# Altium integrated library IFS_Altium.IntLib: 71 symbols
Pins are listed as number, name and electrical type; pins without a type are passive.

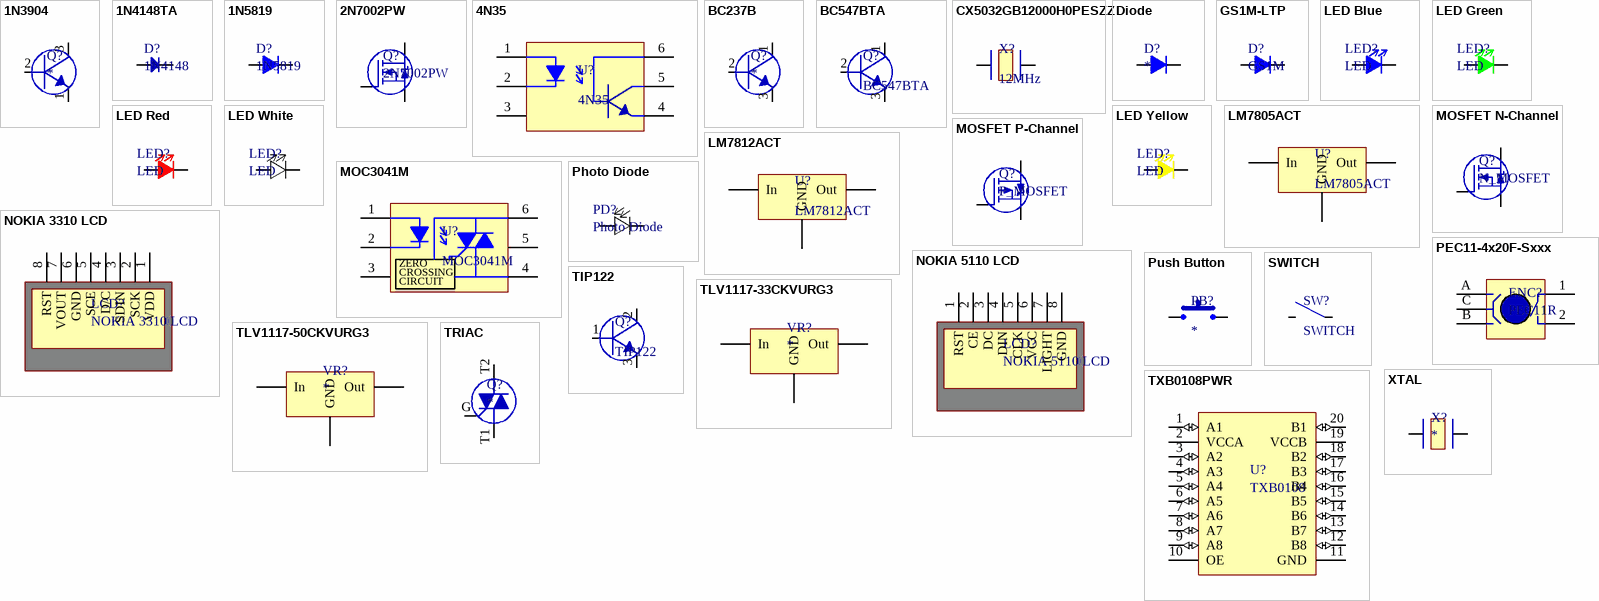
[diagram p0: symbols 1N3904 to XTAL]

## 1N3904
designator Q?
1N3904 NPN Transistor
footprint TO92-2.54 (TO92, 2.54 pitch)
pins: 1, 2, 3

## 1N4148TA
designator D?, comment 1N4148
Diodes - General Purpose, Power, Switching Hi Conductance Fast; Manufacturer: Fairchild Semiconductor; Manufacturer Part Number: 1N4148TA; Configuration: Single; Forward Continuous Current: 0.2 A; Max Surge Current: 4 A; Recovery Time: 4 ns; Forward Voltage Drop: 1 V; Maximum Power Dissipation: 0.5 W; Peak Reverse Voltage: 100 V
footprint DO-35 Glass (DO-35 Glass 4mils)
pins: 1, 2

## 1N5819
designator D?
Schottky diode
footprint DO-214AC (DO-214AC, SMA)
pins: 1, 2

## 2N7002PW
designator Q?
MOSFET 60V 0.3A N-CHANNEL TRENCH MOSFET; Manufacturer: NXP Semiconductors; Manufacturer Part Number: 2N7002PW,115; Configuration: Single; Continuous Drain Current: 310 mA; Rds On: 1 Ohms; Fall Time: 4 ns; Pd - Power Dissipation: 260 mW; Qg - Gate Charge: 0.6 nC; Typical Turn-Off Delay Time: 10 ns; Vgs - Gate-Source Breakdown Voltage: 20 V
footprint SOT323 (SOT323, 3 pins)
pins: 1 G, 2 S, 3 D

## 4N35
designator U?
Transistor Output Optocouplers PTR 100%, 3.5KV; Manufacturer: Lite-On; Input Type: DC; Isolation Voltage: 3550 Vrms; Output Device: NPN Phototransistor; Maximum Collector Current: 100 mA; Maximum Collector Emitter Saturation Voltage: 0.3 V; Maximum Collector Emitter Voltage: 30 V; Maximum Forward Diode Voltage: 1.5 V; Maximum Input Diode Current: 60 mA; Maximum Power Dissipation: 350 mW; Maximum Reverse Diode Voltage: 6 V; Number of Channels per Chip: 1 Channel
footprint PDIP6-300
pins: 1 (power), 2, 3, 4, 5, 6

## BC237B
designator Q?
BC237B NPN Transistor
footprint TO92-2.54 (TO92, 2.54 pitch)
pins: 1, 2, 3

## BC547BTA
designator Q?
TRANS NPN 45V 100MA TO-92; Manufacturer: Fairchild Semiconductor; Vce Saturation (Max) @ Ib, Ic: 600mV @ 5mA, 100mA; DC Current Gain (hFE) (Min) @ Ic, Vce: 200 @ 2mA, 5V; Power - Max: 500mW; Frequency - Transition: 300MHz
footprint TO92-2.54 (TO92, 2.54 pitch)
pins: 1, 2, 3

## CX5032GB12000H0PESZZ
designator X?, comment 12MHz
Crystals 12000kHz 12pF; Manufacturer: AVX; Manufacturer Part Number: CX5032GB12000H0PESZZ; Frequency Stability: 20 PPM
footprint 2-SMD
pins: 1, 2

## Diode
designator D?
Diode, generic
pins: 1, 2

## GS1M-LTP
designator D?, comment GS1M
Rectifiers 1000V,1A; Manufacturer: Micro Commercial Components (MCC); Manufacturer Part Number: GS1M-LTP; Max Surge Current: 30 A; Reverse Current IR: 10 uA
footprint DO-214AC (DO-214AC, SMA)
pins: 1, 2

## LED Blue
designator LED?, comment LED
LED Blue
footprint LED Blue 3mm TH V
pins: 1, 2

## LED Green
designator LED?, comment LED
LED Green
footprint LED Green 3mm TH V
pins: 1, 2

## LED Red
designator LED?, comment LED
LED Red
footprint LED Red 3mm TH V
pins: 1, 2

## LED White
designator LED?, comment LED
LED White
footprint LED White 3mm TH V
pins: 1, 2

## LED Yellow
designator LED?, comment LED
LED Yellow
footprint LED Yellow 3mm TH V
pins: 1, 2

## LM7805ACT
designator U?
IC REG LDO 5V 1A TO220-3; Manufacturer: Fairchild Semiconductor; Regulator Topology: Positive Fixed; Voltage - Dropout (Typical): 2V @ 1A; Number of Regulators: 1; Voltage - Input: Up to 35V
footprint TO220-3 (TO220, 3 Pins)
pins: 1 In (power), 2 GND (power), 3 Out (power)

## LM7812ACT
designator U?
IC REG LDO 12V 1A TO220-3; Manufacturer: Fairchild Semiconductor; Regulator Topology: Positive Fixed; Voltage - Dropout (Typical): 2V @ 1A; Number of Regulators: 1; Voltage - Input: Up to 35V
footprint TO220-3 (TO220, 3 Pins)
pins: 1 In (power), 2 GND (power), 3 Out (power)

## MOC3041M
designator U?
Triac & SCR Output Optocouplers DIP-6 ZERO TRIAC; Manufacturer: Fairchild Semiconductor; Isolation Voltage: 5250 Vrms; Output Device: PhotoTriac; Output Type: AC; Forward Current: 60 mA; Forward Voltage: 1.25 V; Power Dissipation: 250 mW; Maximum Trigger Current: 15 mA; Number of Channels per Chip: 1 Channel; Off-state Output Voltage - VDRM: 400 V; Zero-Crossing Circuit: With Zero-Crossing Circuit; Zero-Crossing Voltage: 20 V
footprint PDIP6-300-W (PDIP6-300 White)
pins: 1 (power), 2, 3, 4, 5, 6

## MOSFET N-Channel
designator Q?, comment N_MOSFET
Generic N-Channel MOSFET
footprint SOT323 (SOT323, 3 pins)
pins: 1 G, 2 S, 3 D

## MOSFET P-Channel
designator Q?, comment P_MOSFET
Generic P-Channel MOSFET
footprint SOT323 (SOT323, 3 pins)
pins: 1 G, 2 S, 3 D

## NOKIA 3310 LCD
designator LCD?
footprint NOKIA 3310 LCD
pins: 1 VDD, 2 SCK, 3 SDIN, 4 D/C, 5 SCE, 6 GND, 7 VOUT, 8 RST

## NOKIA 5110 LCD
designator LCD?
footprint NOKIA 5110 LCD
pins: 1 RST, 2 CE, 3 DC, 4 DIN, 5 CLK, 6 VCC, 7 LIGHT, 8 GND

## PEC11-4x20F-Sxxx
designator ENC?, comment PEC11R
Encoders 20mm SHAFT w/SWITCH; Manufacturer: Bourns; Manufacturer Part Number: PEC11R-4220F-S0024; Number of Detents: 24; Output: Quadrature; Resolution: 24 PPR; With Switch: Switch; Number of Channels: 2 Channel; Shaft Type: Flatted; Product Status: New Product
footprint PEC11-4x20F-Sxxx (Incrmental Encoder with momentary puch switch)
pins: 1, 2, A, B, C, GND (power) hidden to GND

## Photo Diode
designator PD?
footprint LED White 3mm TH V
pins: 1, 2

## Push Button
designator PB?
Push Button
footprint Tack Switch 6x6 1mm TH (Tack Switch 6x6mm, 1mm button height TH)
pins: 1, 2

## SWITCH
designator SW?
Switch, generic
footprint 1x2x5.08 Pin Header TH V
pins: 1, 2

## TIP122
designator Q?
TRANS NPN DARL 100V 5A TO-220; Manufacturer: Fairchild Semiconductor; Transistor Type: NPN - Darlington; Vce Saturation (Max) @ Ib, Ic: 4V @ 20mA, 5A; Current - Collector Cutoff (Max): 500µA; DC Current Gain (hFE) (Min) @ Ic, Vce: 1000 @ 3A, 3V; Power - Max: 2W
footprint TO220-3 (TO220, 3 Pins)
pins: 1, 2, 3

## TLV1117-33CKVURG3
designator VR?
LDO Voltage Regulators Sgl Output LDO 800mA Fixed Int Crnt limit; Manufacturer: Texas Instruments; Input Bias Current - Max: 5 mA; Input Voltage MAX: 15 V; Number of Outputs: 1 Output; Output Voltage: 3.3 V; Dropout Voltage - Max: 1.2 V at 100 mA, 1.25 V at 500 mA, 1.3 V at 800 mA; Input Voltage MIN: + 4.7 V; Line Regulation: 0.2 %; Load Regulation: 0.4 %
footprint TO252-2 (TO252, 2 Pins)
pins: 1 GND, 2 Out, 3 In

## TLV1117-50CKVURG3
designator VR?
LDO Voltage Regulators Sgl Output LDO 800mA Fixed Int Crnt limit; Manufacturer: Texas Instruments; Manufacturer Part Number: TLV1117-50CKVURG3; Input Bias Current - Max: 5 mA; Input Voltage MAX: 15 V; Number of Outputs: 1 Output; Output Voltage: 5 V; Dropout Voltage - Max: 1.2 V at 100 mA, 1.25 V at 500 mA, 1.3 V at 800 mA; Input Voltage MIN: + 6.4 V; Line Regulation: 0.2 %; Load Regulation: 0.4 %
footprint TO252-2 (TO252, 2 Pins)
pins: 1 GND, 2 Out, 3 In

## TRIAC
designator Q?
TRIAC, Generic
pins: G, T1, T2

## TXB0108PWR
designator U?, comment TXB0108
Translation - Voltage Levels 8-Bit Bi-directional; Manufacturer: Texas Instruments; Manufacturer Part Number: TXB0108PWR; Propagation Delay Time: 9.5 ns; Supply Voltage - Max: 3.6 V, 5.5 V; Supply Voltage - Min: 1.2 V, 1.65 V
footprint TSSOP20
pins: 1 A1 (io), 2 VCCA (power), 3 A2 (io), 4 A3 (io), 5 A4 (io), 6 A5 (io), 7 A6 (io), 8 A7 (io), 9 A8 (io), 10 OE, 11 GND (power), 12 B8 (io), 13 B7 (io), 14 B6 (io), 15 B5 (io), 16 B4 (io), 17 B3 (io), 18 B2 (io), 19 VCCB (power), 20 B1 (io)

## XTAL
designator X?
Crystal, Generic
footprint HC-49U (HC-49U XTAL)
footprint HC-49US (HC-49US XTAL)
footprint HC-49US - SMD (HC-49US XTAL)
footprint Cilindrical-H-SMD (Cilindrical canned XTAL, Horizontal, SMD)
footprint 2-SMD
pins: 1, 2


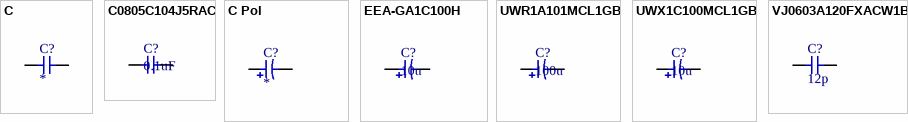
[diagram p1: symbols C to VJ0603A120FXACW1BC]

## C
designator C?
Capacitor, generic
footprint C Disc 5x2.5-2.5
footprint C0603-0.80 (Capacitor Chip 0603 Height 0.80mm)
footprint C0805-0.80 (Capacitor Chip 0805 Height 0.80)
footprint C0805-1.25 (Capacitor Chip 0805 Height 1.25mm)
footprint C1206-0.80 (Capacitor Chip 1206 Height 0.80mm)
footprint C1206-1.00 (Capacitor Chip 1206 Height 1.00mm)
footprint C1206-1.25 (Capacitor Chip 1206 Height 1.25mm)
footprint C1206-1.60 (Capacitor Chip 1206 Height 1.60mm)
footprint C1210-0.80 (Capacitor Chip 1210 Height 0.80mm)
footprint C1210-1.00 (Capacitor Chip 1210 Height 1.00mm)
footprint C1210-1.25 (Capacitor Chip 1210 Height 1.25mm)
footprint C1210-1.60 (Capacitor Chip 1210 Height 1.60mm)
footprint C1210-1.90 (Capacitor Chip 1210 Height 1.90mm)
footprint C1210-2.10 (Capacitor Chip 1210 Height 2.10mm)
footprint C1210-2.50 (Capacitor Chip 1210 Height 2.50mm)
footprint C Disc 8x2.5-5.0 (C Disc 5x2.5-5.0)
pins: 1, 2

## C0805C104J5RAC
designator C?, comment 0.1uF
Multilayer Ceramic Capacitors MLCC - SMD/SMT 50volts 0.1uF 5% X7R; Manufacturer: Kemet; Manufacturer Part Number: C0805C104J5RAC; Type: SMD MLCCs X7R, Commercial; Voltage Rating: 50 V; Case Height: 0.9 mm; Case Length: 2 mm; Case Width: 1.2 mm; Class: 2; Dissipation Factor DF: 2.5
footprint C0805-0.80 (Capacitor Chip 0805 Height 0.80)
pins: 1, 2

## C Pol
designator C?
Capacitor, polarized, generic
footprint C Elec SMD 6.3x5.4 (C Elec SMD 6.3x5.4, Generic Value)
footprint C Elec TH V 4x7-2.5 (C Elec TH 4x7 2.5mm pitch)
footprint C Elec TH V 18x35-7.5 (C Elec TH 18x35 7.5mm pitch)
pins: 1, 2

## EEA-GA1C100H
designator C?, comment 10u
Aluminium Electrolytic Capacitors - Leaded 16volts 10uF 4X7mm L/S=2.5mm Ammo STR; Manufacturer: Panasonic; Manufacturer Part Number: EEA-GA1C100H; Tolerance: 20 %; Voltage Rating DC: 16 V; Leakage Current: 3 uA; Case Diameter: 4 mm; Case Length: 7 mm; Load Life: 1000 h; Ripple Current: 30 mA
footprint C Elec TH V 4x7-2.5 (C Elec TH 4x7 2.5mm pitch)
pins: 1, 2

## UWR1A101MCL1GB
designator C?, comment 100u
Aluminium Electrolytic Capacitors - SMD 100UF    10V; Manufacturer: Nichicon; Manufacturer Part Number: UWR1A101MCL1GB; Tolerance: 20 %; Leakage Current: 75.2 uA; Case Diameter: 5 mm; Case Height: 5.5 mm; Dissipation Factor DF: 0.24; Load Life: 2000 h; Ripple Current: 54 mA; Product Status: New Product
footprint C Elec SMD 6.3x5.4-100u-10V (C Elec SMD 6.3x5.4, 100uF, 10V)
pins: 1, 2

## UWX1C100MCL1GB
designator C?, comment 10u
Aluminium Electrolytic Capacitors - SMD 16volts 10uF 20%; Manufacturer: Nichicon; Manufacturer Part Number: UWX1C100MCL1GB; Type: SMD Aluminum Electrolytic Capacitors; Voltage Rating DC: 16 V; Leakage Current: 3 uA; Case Diameter: 4 mm; Case Length: 5.4 mm; Dissipation Factor DF: 0.16; Load Life: 2000 h; Ripple Current: 23 mA
footprint C Elec SMD 4x5.4-10u-16V (C Elec SMD 4x5.4, 10uF, 16V)
pins: 1, 2

## VJ0603A120FXACW1BC
designator C?, comment 12p
Multilayer Ceramic Capacitors MLCC - SMD/SMT 0603 12pF 50volts C0G 1%; Manufacturer: Vishay / Vitramon; Manufacturer Part Number: VJ0603A120FXACW1BC; Type: Ultra Small Commodity MLCCs; Voltage Rating: 50 V; Case Height: 0.95 mm; Case Length: 1.6 mm; Case Width: 0.8 mm; Dissipation Factor DF: 0.1; Temperature Coefficient / Code: C0G (NP0)
footprint C0603-0.80 (Capacitor Chip 0603 Height 0.80mm)
pins: 1, 2


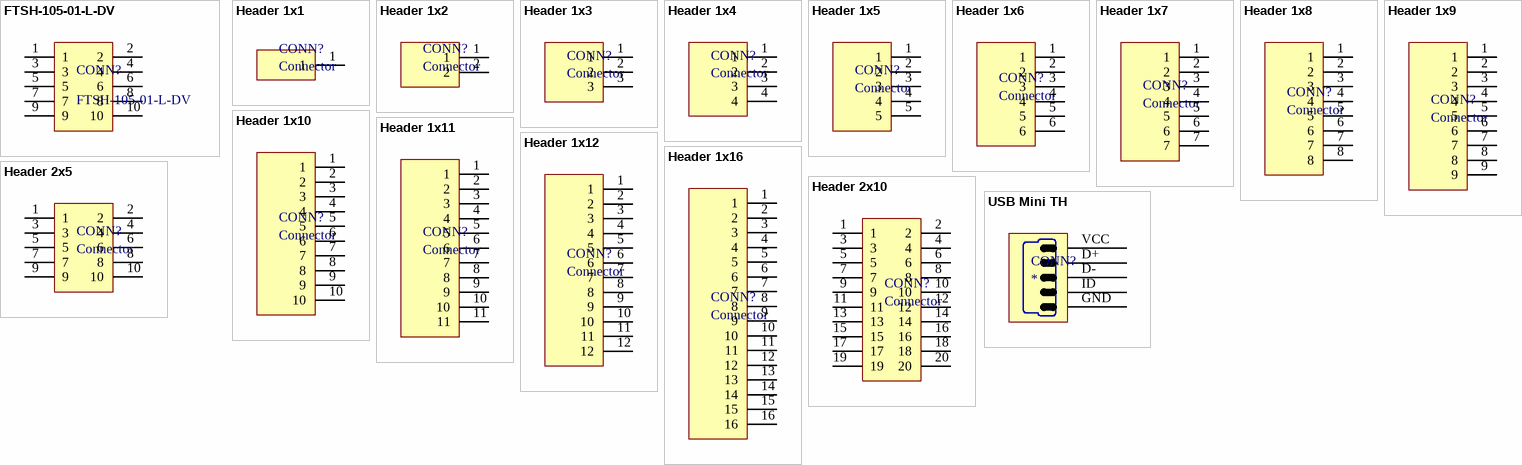
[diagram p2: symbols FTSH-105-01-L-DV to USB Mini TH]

## FTSH-105-01-L-DV
designator CONN?
SAMTEC - FTSH-105-01-L-DV - MACHO, 1,27 MM, SMD, 10 VÍAS; Serie: FTSH; Espaciado, Paso: 1.27; Núm. de Filas: 2; Núm. de Contactos: 10; Género: Conector; Contacto, Terminación: Soldar; Contacto, Chapado: Oro; Contacto, Material: Fosfuro de Bronce; Sustancia Extremadamente Preocupante (SVHC): No SVHC (16-Dec-2013); Intensidad Nominal: 1.75; Método de Terminación: Soldable; Temperatura de Trabajo Máx.: 125; Temperatura de Trabajo Mín.: -55
footprint FTSH-105-01-L-DV
pins: 1, 2, 3, 4, 5, 6, 7, 8, 9, 10

## Header 1x1
designator CONN?, comment Connector
footprint 1x1x2.54 Pin Header TH V (1x1x2.54 Pin Header TH Vertical)
pins: 1

## Header 1x2
designator CONN?, comment Connector
footprint 1x2x2.54 Pin Header TH V
pins: 1, 2

## Header 1x3
designator CONN?, comment Connector
footprint 1x3x2.54 Pin Header TH V
pins: 1, 2, 3

## Header 1x4
designator CONN?, comment Connector
footprint 1x4x2.54 Pin Header TH V
pins: 1, 2, 3, 4

## Header 1x5
designator CONN?, comment Connector
footprint 1x5x2.54 Pin Header TH V
pins: 1, 2, 3, 4, 5

## Header 1x6
designator CONN?, comment Connector
footprint 1x6x2.54 Pin Header TH V
pins: 1, 2, 3, 4, 5, 6

## Header 1x7
designator CONN?, comment Connector
footprint 1x7x2.54 Pin Header TH V
pins: 1, 2, 3, 4, 5, 6, 7

## Header 1x8
designator CONN?, comment Connector
footprint 1x8x2.54 Pin Header TH V
pins: 1, 2, 3, 4, 5, 6, 7, 8

## Header 1x9
designator CONN?, comment Connector
footprint 1x9x2.54 Pin Header TH V
pins: 1, 2, 3, 4, 5, 6, 7, 8, 9

## Header 1x10
designator CONN?, comment Connector
footprint 1x10x2.54 Pin Header TH V
pins: 1, 2, 3, 4, 5, 6, 7, 8, 9, 10

## Header 1x11
designator CONN?, comment Connector
footprint 1x11x2.54 Pin Header TH V
pins: 1, 2, 3, 4, 5, 6, 7, 8, 9, 10, 11

## Header 1x12
designator CONN?, comment Connector
footprint 1x12x2.54 Pin Header TH V
pins: 1, 2, 3, 4, 5, 6, 7, 8, 9, 10, 11, 12

## Header 1x16
designator CONN?, comment Connector
footprint 1x16x2.54 Pin Header TH V
pins: 1, 2, 3, 4, 5, 6, 7, 8, 9, 10, 11, 12, 13, 14, 15, 16

## Header 2x5
designator CONN?, comment Connector
footprint 2x5x2.54 Pin Header TH V
pins: 1, 2, 3, 4, 5, 6, 7, 8, 9, 10

## Header 2x10
designator CONN?, comment Connector
footprint 2x10x2.54 Pin Header TH V
pins: 1, 2, 3, 4, 5, 6, 7, 8, 9, 10, 11, 12, 13, 14, 15, 16, 17, 18, 19, 20

## USB Mini TH
designator CONN?
footprint USB Mini TH (USB Mini MOLEX 548190519)
pins: D+ 2, D- 3, GND 5, ID 4, VCC


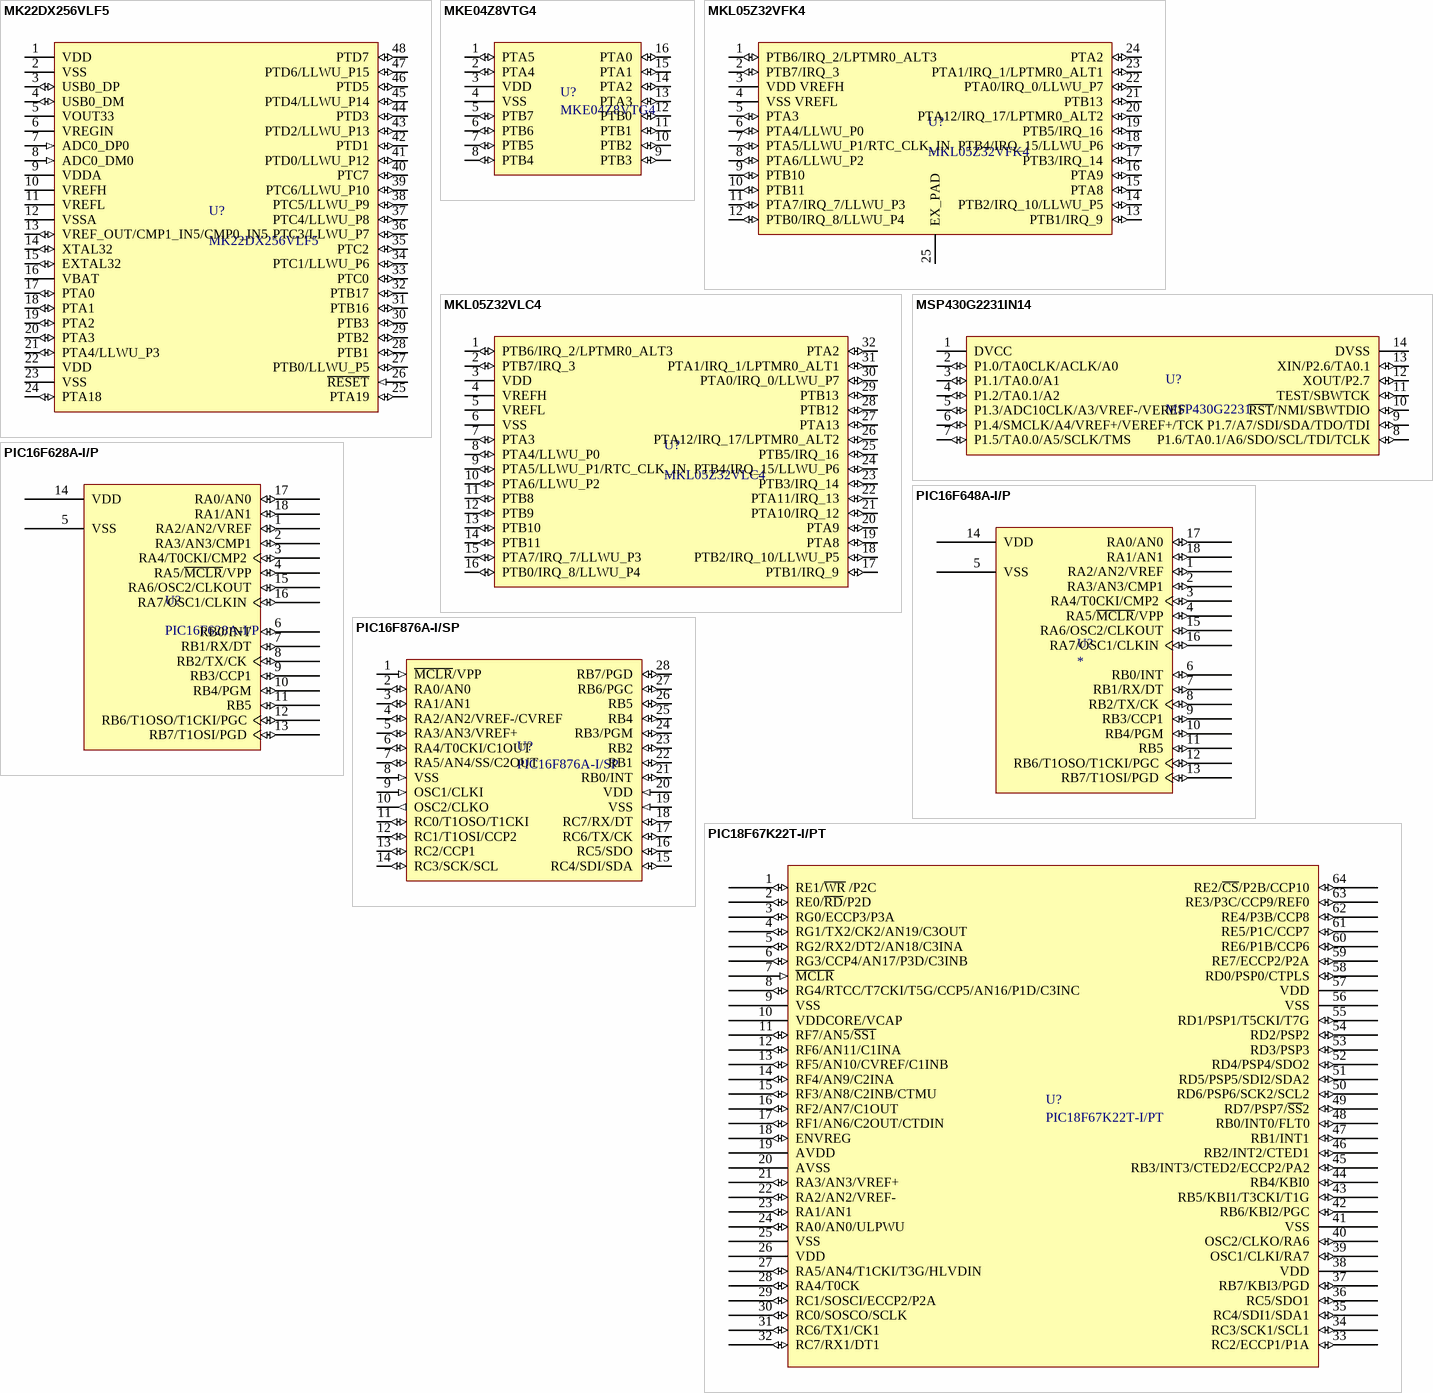
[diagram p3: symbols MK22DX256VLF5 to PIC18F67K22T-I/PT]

## MK22DX256VLF5
designator U?
ARM Microcontrollers - MCU ARM+256Kb +USB; Manufacturer: Freescale Semiconductor
footprint LQFP48-7x7x1.4-0.50 (LQFP 48 pins, 7x7x1.4mm body, 0.50 pitch)
pins: 1 VDD (power), 2 VSS (power), 3 USB0_DP (io), 4 USB0_DM (io), 5 VOUT33 (power), 6 VREGIN (power), 7 ADC0_DP0 (in), 8 ADC0_DM0 (in), 9 VDDA (power), 10 VREFH (power), 11 VREFL (power), 12 VSSA (power), 13 VREF_OUT/CMP1_IN5/CMP0_IN5 (io), 14 XTAL32 (io), 15 EXTAL32 (io), 16 VBAT (power), 17 PTA0 (io), 18 PTA1 (io), 19 PTA2 (io), 20 PTA3 (io), 21 PTA4/LLWU_P3 (io), 22 VDD (power), 23 VSS (power), 24 PTA18 (io), 25 PTA19 (io), 26 ~{RESET} (in), 27 PTB0/LLWU_P5 (io), 28 PTB1 (io), 29 PTB2 (io), 30 PTB3 (io), 31 PTB16 (io), 32 PTB17 (io), 33 PTC0 (io), 34 PTC1/LLWU_P6 (io), 35 PTC2 (io), 36 PTC3/LLWU_P7 (io), 37 PTC4/LLWU_P8 (io), 38 PTC5/LLWU_P9 (io), 39 PTC6/LLWU_P10 (io), 40 PTC7 (io), 41 PTD0/LLWU_P12 (io), 42 PTD1 (io), 43 PTD2/LLWU_P13 (io), 44 PTD3 (io), 45 PTD4/LLWU_P14 (io), 46 PTD5 (io), 47 PTD6/LLWU_P15 (io), 48 PTD7 (io)

## MKE04Z8VTG4
designator U?
ARM Microcontrollers - MCU M0 + 8K FLASH 48MHZ; Manufacturer: Freescale Semiconductor; A/D Bit Size: 12 bit; A/D Channels Available: 12; Data RAM Size: 1 kB; Data RAM Type: RAM; Interface Type: I2C, SPI, UART; Number of I/Os: 22 I/O; Program Memory Size: 8 kB; Core: ARM Cortex M0; Data Bus Width: 32 bit; Number of Timers: 5 Timer; On-Chip DAC: Without DAC; Operating Supply Voltage: 2.7 V to 5.5 V; Product Status: New at Mouser
footprint TSSOP16 (TSSOP 16 Pin)
pins: 1 PTA5 (io), 2 PTA4 (io), 3 VDD (power), 4 VSS (power), 5 PTB7 (io), 6 PTB6 (io), 7 PTB5 (io), 8 PTB4 (io), 9 PTB3 (io), 10 PTB2 (io), 11 PTB1 (io), 12 PTB0 (io), 13 PTA3 (io), 14 PTA2 (io), 15 PTA1 (io), 16 PTA0 (io)

## MKL05Z32VFK4
designator U?
ARM Microcontrollers - MCU Kinetis L ARM M0+ 32k Flash; Manufacturer: Freescale Semiconductor; Data RAM Size: 4 kB; Program Memory Size: 32 kB; Core: ARM Cortex M0; Data Bus Width: 32 bit; Maximum Clock Frequency: 48 MHz; On-Chip ADC: Yes; Operating Supply Voltage: 1.71 V to 3.6 V; Product Status: New at Mouser
footprint QFN24-4x4x0.9-0.50 (QFN 24 Pin, 4x4x0.9mm, 0.50 Pitch)
pins: 1 PTB6/IRQ_2/LPTMR0_ALT3 (io), 2 PTB7/IRQ_3 (io), 3 VDD VREFH (power), 4 VSS VREFL (power), 5 PTA3 (io), 6 PTA4/LLWU_P0 (io), 7 PTA5/LLWU_P1/RTC_CLK_IN (io), 8 PTA6/LLWU_P2 (io), 9 PTB10 (io), 10 PTB11 (io), 11 PTA7/IRQ_7/LLWU_P3 (io), 12 PTB0/IRQ_8/LLWU_P4 (io), 13 PTB1/IRQ_9 (io), 14 PTB2/IRQ_10/LLWU_P5 (io), 15 PTA8 (io), 16 PTA9 (io), 17 PTB3/IRQ_14 (io), 18 PTB4/IRQ_15/LLWU_P6 (io), 19 PTB5/IRQ_16 (io), 20 PTA12/IRQ_17/LPTMR0_ALT2 (io), 21 PTB13 (io), 22 PTA0/IRQ_0/LLWU_P7 (io), 23 PTA1/IRQ_1/LPTMR0_ALT1 (io), 24 PTA2 (io), 25 EX_PAD (power)

## MKL05Z32VLC4
designator U?
ARM Microcontrollers - MCU ARM M0+core,32KFlash; Manufacturer: Freescale Semiconductor; Program Memory Type: Flash; Data RAM Size: 4 kB; Data Ram Type: RAM; Interface Type: I2C, LPUART, SPI; Program Memory Size: 32 kB; Core: ARM Cortex M0; Data Bus Width: 32 bit; Maximum Clock Frequency: 48 MHz; Number of Programmable I/Os: 28; Number of Timers: 2; On-Chip DAC: Yes; Operating Supply Voltage: 1.7 V to 3.6 V; Product Status: New Technology
footprint LQFP32-7x7x1.4-0.8 (LQFP 32 pins, 7x7x1.4mm body, 0.80 pitch)
pins: 1 PTB6/IRQ_2/LPTMR0_ALT3 (io), 2 PTB7/IRQ_3 (io), 3 VDD (power), 4 VREFH (power), 5 VREFL (power), 6 VSS (power), 7 PTA3 (io), 8 PTA4/LLWU_P0 (io), 9 PTA5/LLWU_P1/RTC_CLK_IN (io), 10 PTA6/LLWU_P2 (io), 11 PTB8 (io), 12 PTB9 (io), 13 PTB10 (io), 14 PTB11 (io), 15 PTA7/IRQ_7/LLWU_P3 (io), 16 PTB0/IRQ_8/LLWU_P4 (io), 17 PTB1/IRQ_9 (io), 18 PTB2/IRQ_10/LLWU_P5 (io), 19 PTA8 (io), 20 PTA9 (io), 21 PTA10/IRQ_12 (io), 22 PTA11/IRQ_13 (io), 23 PTB3/IRQ_14 (io), 24 PTB4/IRQ_15/LLWU_P6 (io), 25 PTB5/IRQ_16 (io), 26 PTA12/IRQ_17/LPTMR0_ALT2 (io), 27 PTA13 (io), 28 PTB12 (io), 29 PTB13 (io), 30 PTA0/IRQ_0/LLWU_P7 (io), 31 PTA1/IRQ_1/LPTMR0_ALT1 (io), 32 PTA2 (io)

## MSP430G2231IN14
designator U?, comment MSP430G2231
16-bit Microcontrollers - MCU Ultra low power Microcontroller; Manufacturer: Texas Instruments; Manufacturer Part Number: MSP430G2231IN14; Program Memory Type: Flash; Data RAM Size: 128 B; Data RAM Type: SRAM; Interface Type: I2C, SPI; Program Memory Size: 2 kB; Core: MSP430; Data Bus Width: 16 bit; Maximum Clock Frequency: 16 MHz; Number of Programmable I/Os: 10; Number of Timers: 1; On-Chip ADC: Yes; Operating Supply Voltage: 1.8 V to 3.6 V; Processor Series: 2 Series; Product Status: New Technology
footprint PDIP14-300
pins: 1 DVCC (power), 2 P1.0/TA0CLK/ACLK/A0 (io), 3 P1.1/TA0.0/A1 (io), 4 P1.2/TA0.1/A2 (io), 5 P1.3/ADC10CLK/A3/VREF-/VEREF (io), 6 P1.4/SMCLK/A4/VREF+/VEREF+/TCK (io), 7 P1.5/TA0.0/A5/SCLK/TMS (io), 8 P1.6/TA0.1/A6/SDO/SCL/TDI/TCLK (io), 9 P1.7/A7/SDI/SDA/TDO/TDI (io), 10 ~{RST}/NMI/SBWTDIO (io), 11 TEST/SBWTCK (io), 12 XOUT/P2.7 (io), 13 XIN/P2.6/TA0.1 (io), 14 DVSS (power)

## PIC16F628A-I/P
designator U?
8-bit Microcontrollers - MCU 3.5KB 224 RAM 16 I/O; Manufacturer: Microchip Technology; Program Memory Type: Flash; A/D Bit Size: No ADC; Data RAM Size: 224 B; Data ROM Size: 128 B; Interface Type: SCI, USART; Number of I/Os: 16 I/O; Core: PIC; Data Bus Width: 8 bit; Maximum Clock Frequency: 20 MHz; Number of Timers: 3 Timer; On-Chip ADC: No; Operating Supply Voltage: 2 V to 5.5 V; Processor Series: PIC16; Supply Voltage - Max: 5.5 V; Supply Voltage - Min: 3 V
footprint PDIP18-300
pins: 1 RA2/AN2/VREF (io), 2 RA3/AN3/CMP1 (io), 3 RA4/T0CKI/CMP2 (io), 4 RA5/~{MCLR}/VPP (io), 5 VSS (power), 6 RB0/INT (io), 7 RB1/RX/DT (io), 8 RB2/TX/CK (io), 9 RB3/CCP1 (io), 10 RB4/PGM (io), 11 RB5 (io), 12 RB6/T1OSO/T1CKI/PGC (io), 13 RB7/T1OSI/PGD (io), 14 VDD (power), 15 RA6/OSC2/CLKOUT (io), 16 RA7/OSC1/CLKIN (io), 17 RA0/AN0 (io), 18 RA1/AN1 (io)

## PIC16F648A-I/P
designator U?
8-bit Microcontrollers - MCU 7KB 256 RAM 16 I/O; Manufacturer: Microchip Technology; Manufacturer Part Number: PIC16F648A-I/P; Program Memory Type: Flash; Data RAM Size: 256 B; Interface Type: SCI, USART; Program Memory Size: 4 KB; Core: PIC; Data Bus Width: 8 bit; Maximum Clock Frequency: 20 MHz; Number of Programmable I/Os: 16; Number of Timers: 3; On-Chip ADC: No; Operating Supply Voltage: 2 V to 5.5 V; Processor Series: PIC16; Supply Voltage - Max: 5.5 V; Supply Voltage - Min: 3 V
footprint PDIP18-300
pins: 1 RA2/AN2/VREF (io), 2 RA3/AN3/CMP1 (io), 3 RA4/T0CKI/CMP2 (io), 4 RA5/~{MCLR}/VPP (io), 5 VSS (power), 6 RB0/INT (io), 7 RB1/RX/DT (io), 8 RB2/TX/CK (io), 9 RB3/CCP1 (io), 10 RB4/PGM (io), 11 RB5 (io), 12 RB6/T1OSO/T1CKI/PGC (io), 13 RB7/T1OSI/PGD (io), 14 VDD (power), 15 RA6/OSC2/CLKOUT (io), 16 RA7/OSC1/CLKIN (io), 17 RA0/AN0 (io), 18 RA1/AN1 (io)

## PIC16F876A-I/SP
designator U?
8-bit Microcontrollers - MCU 14KB 368 RAM 22 I/O; Manufacturer: Microchip Technology; Program Memory Type: Flash; A/D Bit Size: 10 bit; A/D Channels Available: 5; Data RAM Size: 368 B; Data ROM Size: 256 B; Interface Type: I2C, SPI, USART; Core: PIC; Data Bus Width: 8 bit; Maximum Clock Frequency: 20 MHz; Number of Programmable I/Os: 22; Number of Timers: 3; On-Chip ADC: Yes; Operating Supply Voltage: 2 V to 5.5 V; Processor Series: PIC16; Supply Voltage - Max: 5.5 V; Supply Voltage - Min: 4 V
footprint PDIP28-300
pins: 1 ~{MCLR}/VPP (in), 2 RA0/AN0 (io), 3 RA1/AN1 (io), 4 RA2/AN2/VREF-/CVREF (io), 5 RA3/AN3/VREF+ (io), 6 RA4/T0CKI/C1OUT (io), 7 RA5/AN4/SS/C2OUT (io), 8 VSS (in), 9 OSC1/CLKI (in), 10 OSC2/CLKO (out), 11 RC0/T1OSO/T1CKI (io), 12 RC1/T1OSI/CCP2 (io), 13 RC2/CCP1 (io), 14 RC3/SCK/SCL (io), 15 RC4/SDI/SDA (io), 16 RC5/SDO (io), 17 RC6/TX/CK (io), 18 RC7/RX/DT (io), 19 VSS (in), 20 VDD (in), 21 RB0/INT (io), 22 RB1 (io), 23 RB2 (io), 24 RB3/PGM (io), 25 RB4 (io), 26 RB5 (io), 27 RB6/PGC (io), 28 RB7/PGD (io)

## PIC18F67K22T-I/PT
designator U?
8-bit Microcontrollers - MCU 128kB Flash 4kB RAM; Manufacturer: Microchip Technology; A/D Bit Size: 12 bit; A/D Channels Available: 16; Data RAM Size: 3 kB; Data RAM Type: SRAM; Interface Type: I2C, SPI; Number of I/Os: 53 I/O; Core: PIC; Data Bus Width: 8 bit; Maximum Clock Frequency: 64 MHz; Number of Timers: 11 Timer; On-Chip ADC: Yes; Operating Supply Voltage: 1.8 V to 5.5 V; Processor Series: PIC18
footprint TQFP64-10x10-0.50 (TQFP 64 pins, 10x10mm body, 0.50 pitch)
pins: 1 RE1/~{WR} /P2C (io), 2 RE0/~{RD}/P2D (io), 3 RG0/ECCP3/P3A (io), 4 RG1/TX2/CK2/AN19/C3OUT (io), 5 RG2/RX2/DT2/AN18/C3INA (io), 6 RG3/CCP4/AN17/P3D/C3INB (io), 7 ~{MCLR} (in), 8 RG4/RTCC/T7CKI/T5G/CCP5/AN16/P1D/C3INC (io), 9 VSS (power), 10 VDDCORE/VCAP (power), 11 RF7/AN5/~{SS1} (io), 12 RF6/AN11/C1INA (io), 13 RF5/AN10/CVREF/C1INB (io), 14 RF4/AN9/C2INA (io), 15 RF3/AN8/C2INB/CTMU (io), 16 RF2/AN7/C1OUT (io), 17 RF1/AN6/C2OUT/CTDIN (io), 18 ENVREG (io), 19 AVDD (power), 20 AVSS (power), 21 RA3/AN3/VREF+ (io), 22 RA2/AN2/VREF- (io), 23 RA1/AN1 (io), 24 RA0/AN0/ULPWU (io), 25 VSS (power), 26 VDD (power), 27 RA5/AN4/T1CKI/T3G/HLVDIN (io), 28 RA4/T0CK (io), 29 RC1/SOSCI/ECCP2/P2A (io), 30 RC0/SOSCO/SCLK (io), 31 RC6/TX1/CK1 (io), 32 RC7/RX1/DT1 (io), 33 RC2/ECCP1/P1A (io), 34 RC3/SCK1/SCL1 (io), 35 RC4/SDI1/SDA1 (io), 36 RC5/SDO1 (io), 37 RB7/KBI3/PGD (io), 38 VDD (power), 39 OSC1/CLKI/RA7 (io), 40 OSC2/CLKO/RA6 (io), 41 VSS (power), 42 RB6/KBI2/PGC (io), 43 RB5/KBI1/T3CKI/T1G (io), 44 RB4/KBI0 (io), 45 RB3/INT3/CTED2/ECCP2/PA2 (io), 46 RB2/INT2/CTED1 (io), 47 RB1/INT1 (io), 48 RB0/INT0/FLT0 (io), 49 RD7/PSP7/~{SS}2 (io), 50 RD6/PSP6/SCK2/SCL2 (io), 51 RD5/PSP5/SDI2/SDA2 (io), 52 RD4/PSP4/SDO2 (io), 53 RD3/PSP3 (io), 54 RD2/PSP2 (io), 55 RD1/PSP1/T5CKI/T7G (io), 56 VSS (power), 57 VDD (power), 58 RD0/PSP0/CTPLS (io), 59 RE7/ECCP2/P2A (io), 60 RE6/P1B/CCP6 (io), 61 RE5/P1C/CCP7 (io), 62 RE4/P3B/CCP8 (io), 63 RE3/P3C/CCP9/REF0 (io), 64 RE2/~{CS}/P2B/CCP10 (io)

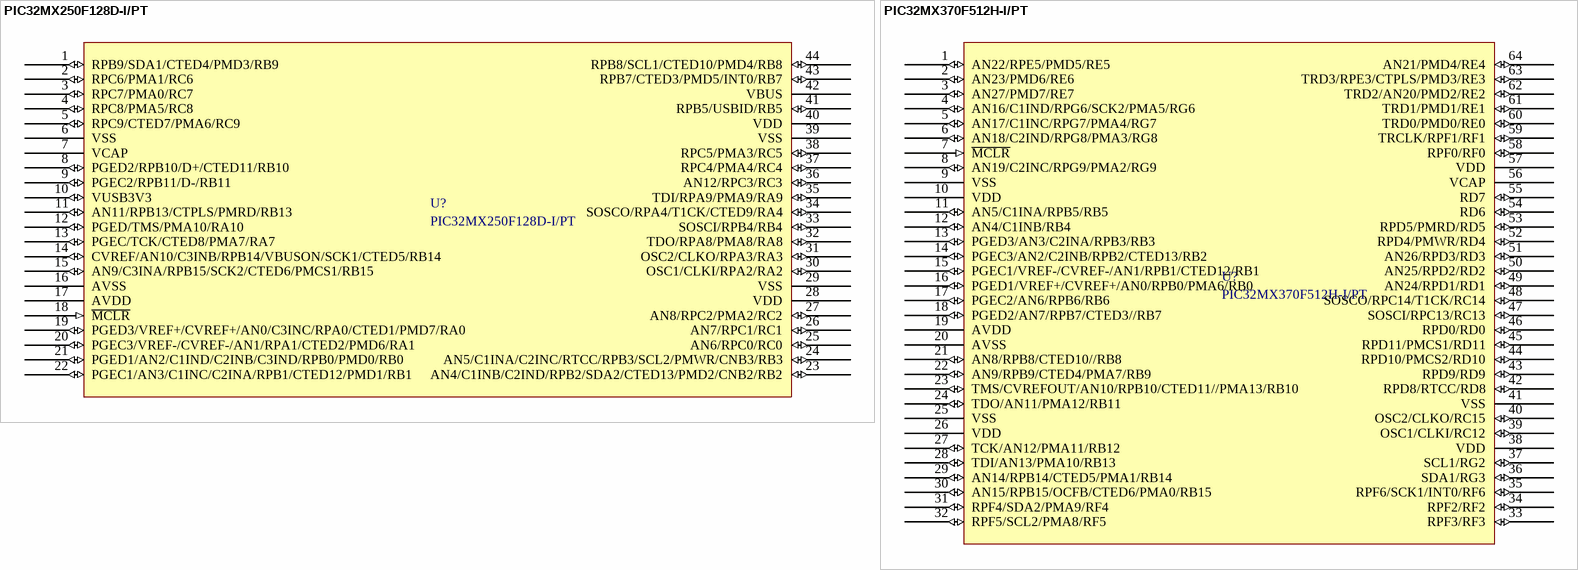
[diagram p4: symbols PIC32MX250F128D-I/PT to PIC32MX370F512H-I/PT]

## PIC32MX250F128D-I/PT
designator U?
Manufacturer: Microchip Technology; Data RAM Size: 32 KB; Program Memory Size: 128 KB; Core: MIPS32 M4K; Data Bus Width: 32 bit; Maximum Clock Frequency: 40 MHz; On-Chip ADC: Yes; Operating Supply Voltage: 2.3 V to 3.6 V
footprint TQFP44-10x10-0.8 (TQFP 44 pins, 10x10mm body, 0.80 pitch)
pins: 1 RPB9/SDA1/CTED4/PMD3/RB9 (io), 2 RPC6/PMA1/RC6 (io), 3 RPC7/PMA0/RC7 (io), 4 RPC8/PMA5/RC8 (io), 5 RPC9/CTED7/PMA6/RC9 (io), 6 VSS (power), 7 VCAP (power), 8 PGED2/RPB10/D+/CTED11/RB10 (io), 9 PGEC2/RPB11/D-/RB11 (io), 10 VUSB3V3 (io), 11 AN11/RPB13/CTPLS/PMRD/RB13 (io), 12 PGED/TMS/PMA10/RA10 (io), 13 PGEC/TCK/CTED8/PMA7/RA7 (io), 14 CVREF/AN10/C3INB/RPB14/VBUSON/SCK1/CTED5/RB14 (io), 15 AN9/C3INA/RPB15/SCK2/CTED6/PMCS1/RB15 (io), 16 AVSS (power), 17 AVDD (power), 18 ~{MCLR} (in), 19 PGED3/VREF+/CVREF+/AN0/C3INC/RPA0/CTED1/PMD7/RA0 (io), 20 PGEC3/VREF-/CVREF-/AN1/RPA1/CTED2/PMD6/RA1 (io), 21 PGED1/AN2/C1IND/C2INB/C3IND/RPB0/PMD0/RB0 (io), 22 PGEC1/AN3/C1INC/C2INA/RPB1/CTED12/PMD1/RB1 (io), 23 AN4/C1INB/C2IND/RPB2/SDA2/CTED13/PMD2/CNB2/RB2 (io), 24 AN5/C1INA/C2INC/RTCC/RPB3/SCL2/PMWR/CNB3/RB3 (io), 25 AN6/RPC0/RC0 (io), 26 AN7/RPC1/RC1 (io), 27 AN8/RPC2/PMA2/RC2 (io), 28 VDD (power), 29 VSS (power), 30 OSC1/CLKI/RPA2/RA2 (io), 31 OSC2/CLKO/RPA3/RA3 (io), 32 TDO/RPA8/PMA8/RA8 (io), 33 SOSCI/RPB4/RB4 (io), 34 SOSCO/RPA4/T1CK/CTED9/RA4 (io), 35 TDI/RPA9/PMA9/RA9 (io), 36 AN12/RPC3/RC3 (io), 37 RPC4/PMA4/RC4 (io), 38 RPC5/PMA3/RC5 (io), 39 VSS (power), 40 VDD (power), 41 RPB5/USBID/RB5 (io), 42 VBUS (power), 43 RPB7/CTED3/PMD5/INT0/RB7 (io), 44 RPB8/SCL1/CTED10/PMD4/RB8 (io)

## PIC32MX370F512H-I/PT
designator U?
32-bit Microcontrollers - MCU 100MHz 2anlg cmp 2I2C 2SPI/I2S 28Ch; Manufacturer: Microchip Technology; Program Memory Type: Flash; A/D Bit Size: 10 bit; A/D Channels Available: 28; Data RAM Size: 128 kB; Data Ram Type: SRAM; Interface Type: I2C, SPI, UART; Program Memory Size: 512 kB; Core: MIPS32 M4K; Data Bus Width: 32 bit; Number of Timers: 7; On-Chip ADC: Yes; On-Chip DAC: No; Operating Supply Voltage: 2.3 V to 3.6 V; Product Status: New Product
footprint TQFP64-10x10-0.50 (TQFP 64 pins, 10x10mm body, 0.50 pitch)
pins: 1 AN22/RPE5/PMD5/RE5 (io), 2 AN23/PMD6/RE6 (io), 3 AN27/PMD7/RE7 (io), 4 AN16/C1IND/RPG6/SCK2/PMA5/RG6 (io), 5 AN17/C1INC/RPG7/PMA4/RG7 (io), 6 AN18/C2IND/RPG8/PMA3/RG8 (io), 7 ~{MCLR} (in), 8 AN19/C2INC/RPG9/PMA2/RG9 (io), 9 VSS (power), 10 VDD (power), 11 AN5/C1INA/RPB5/RB5 (io), 12 AN4/C1INB/RB4 (io), 13 PGED3/AN3/C2INA/RPB3/RB3 (io), 14 PGEC3/AN2/C2INB/RPB2/CTED13/RB2 (io), 15 PGEC1/VREF-/CVREF-/AN1/RPB1/CTED12/RB1 (io), 16 PGED1/VREF+/CVREF+/AN0/RPB0/PMA6/RB0 (io), 17 PGEC2/AN6/RPB6/RB6 (io), 18 PGED2/AN7/RPB7/CTED3//RB7 (io), 19 AVDD (power), 20 AVSS (power), 21 AN8/RPB8/CTED10//RB8 (io), 22 AN9/RPB9/CTED4/PMA7/RB9 (io), 23 TMS/CVREFOUT/AN10/RPB10/CTED11//PMA13/RB10 (io), 24 TDO/AN11/PMA12/RB11 (io), 25 VSS (power), 26 VDD (power), 27 TCK/AN12/PMA11/RB12 (io), 28 TDI/AN13/PMA10/RB13 (io), 29 AN14/RPB14/CTED5/PMA1/RB14 (io), 30 AN15/RPB15/OCFB/CTED6/PMA0/RB15 (io), 31 RPF4/SDA2/PMA9/RF4 (io), 32 RPF5/SCL2/PMA8/RF5 (io), 33 RPF3/RF3 (io), 34 RPF2/RF2 (io), 35 RPF6/SCK1/INT0/RF6 (io), 36 SDA1/RG3 (io), 37 SCL1/RG2 (io), 38 VDD (power), 39 OSC1/CLKI/RC12 (io), 40 OSC2/CLKO/RC15 (io), 41 VSS (power), 42 RPD8/RTCC/RD8 (io), 43 RPD9/RD9 (io), 44 RPD10/PMCS2/RD10 (io), 45 RPD11/PMCS1/RD11 (io), 46 RPD0/RD0 (io), 47 SOSCI/RPC13/RC13 (io), 48 SOSCO/RPC14/T1CK/RC14 (io), 49 AN24/RPD1/RD1 (io), 50 AN25/RPD2/RD2 (io), 51 AN26/RPD3/RD3 (io), 52 RPD4/PMWR/RD4 (io), 53 RPD5/PMRD/RD5 (io), 54 RD6 (io), 55 RD7 (io), 56 VCAP (power), 57 VDD (power), 58 RPF0/RF0 (io), 59 TRCLK/RPF1/RF1 (io), 60 TRD0/PMD0/RE0 (io), 61 TRD1/PMD1/RE1 (io), 62 TRD2/AN20/PMD2/RE2 (io), 63 TRD3/RPE3/CTPLS/PMD3/RE3 (io), 64 AN21/PMD4/RE4 (io)


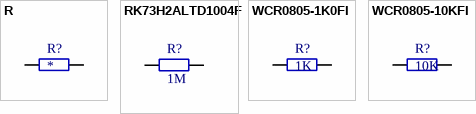
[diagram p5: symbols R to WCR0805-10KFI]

## R
designator R?
Resistor, generic
footprint R Axial 0.6 (Resistor Axial 0.6mils)
footprint R Axial 0.8 (Resistor Axial 0.8mils)
footprint R Axial 0.4 (Resistor Axial 0.4mils)
footprint R0603-0.45 (Resistor Chip 0603 Height 0.45mm)
footprint R0805-0.45 (Resistor Chip 0805 Height 0.45mm)
footprint R1206-0.55 (Resistor Chip 1206 Height 0.55mm)
footprint R1210-0.55 (Resistor Chip 1210 Height 0.55mm)
pins: 1, 2

## RK73H2ALTD1004F
designator R?, comment 1M
Thick Film Resistors - SMD 1/8watts 1Mohms 1%; Manufacturer: KOA Speer; Manufacturer Part Number: RK73H2ALTD1004F; Power Rating: 125 mW (1/8 W); Temperature Coefficient: 100 PPM / C; Voltage Rating: 150 V; Case Height: 0.5 mm; Case Length: 2 mm; Case Width: 1.25 mm
footprint R0805-0.45 (Resistor Chip 0805 Height 0.45mm)
pins: 1, 2

## WCR0805-1K0FI
designator R?, comment 1K
Thick Film Resistors 1K  SMD; Manufacturer: TT electronics; Manufacturer Part Number: WCR0805-1K0FI; Power Rating: 125 mW (1/8 W); Resistance: 1 kOhms; Temperature Coefficient: 100 PPM / C; Tolerance: 1 %; Voltage Rating: 150 V; Case Height: 0.02 in; Case Length: 0.079 in; Case Width: 0.049 in
footprint R0805-0.45 (Resistor Chip 0805 Height 0.45mm)
pins: 1, 2

## WCR0805-10KFI
designator R?, comment 10K
Thick Film Resistors 10K SMD; Manufacturer: TT electronics; Manufacturer Part Number: WCR0805-10KFI; Power Rating: 125 mW (1/8 W); Resistance: 10 kOhms; Temperature Coefficient: 100 PPM / C; Tolerance: 1 %; Voltage Rating: 150 V; Case Height: 0.02 in; Case Length: 0.079 in; Case Width: 0.049 in
footprint R0805-0.45 (Resistor Chip 0805 Height 0.45mm)
pins: 1, 2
